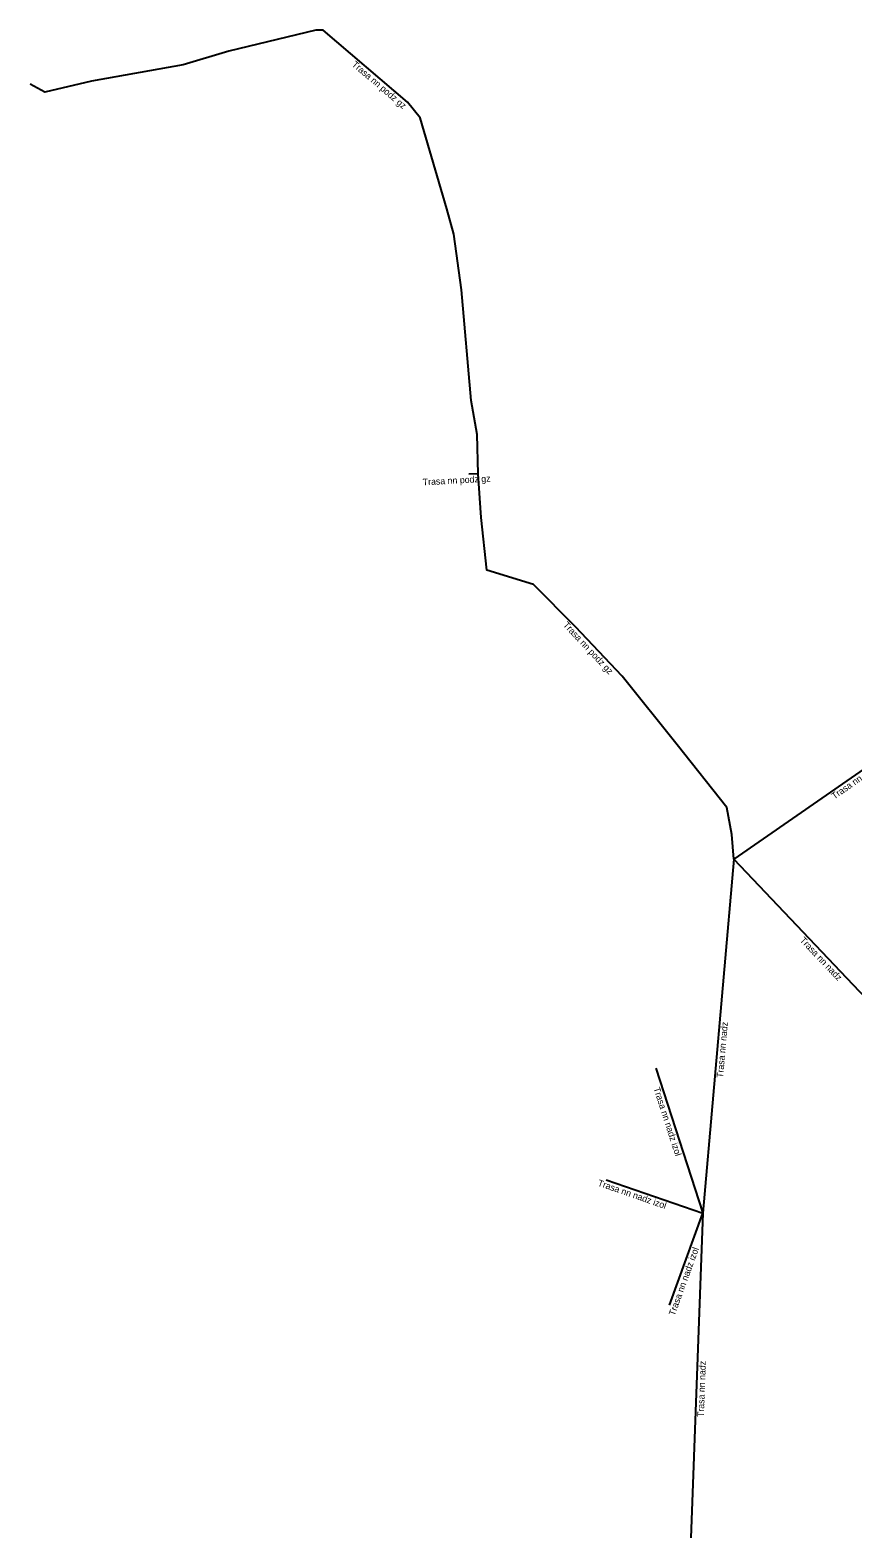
# Model space of a CAD drawing. Extents: x -772942 to -772530, y -1033745 to -1033298.
# Drawn here: x -772942.2 to -772879.6, y -1033618.3 to -1033503.6 of the extents above; entities that cross this region are included whole.
import ezdxf

# ---------------------------------------------------------------- set-up
doc = ezdxf.new("R2010")
doc.units = 0
doc.layers.add('Popiskový text - Ostatní atributy Trasy', color=7, linetype='Continuous')
doc.layers.add('Spojnice NN', color=7, linetype='Continuous')

msp = doc.modelspace()

# ---------------------------------------------------------------- linework, layer by layer
at = {"layer": 'Spojnice NN'}
for points in [[(-772908.07, -1033537.38), (-772908.15, -1033534.39), (-772908.62, -1033531.8), (-772909.34, -1033523.4), (-772909.93, -1033519.17), (-772910.45, -1033517.24), (-772912.49, -1033510.3), (-772913.45, -1033509.11), (-772919.87, -1033503.64), (-772920.43, -1033503.64), (-772927.05, -1033505.25), (-772930.52, -1033506.28), (-772937.51, -1033507.51), (-772941.05, -1033508.35), (-772942.17, -1033507.74)], [(-772908.07, -1033537.38), (-772908.78, -1033537.42)], [(-772888.63, -1033566.69), (-772888.76, -1033564.83), (-772889.14, -1033562.78), (-772892.94, -1033558.01), (-772897.13, -1033552.79), (-772900.67, -1033549.02), (-772903.87, -1033545.8), (-772907.42, -1033544.71), (-772907.85, -1033540.72), (-772908.07, -1033537.38)], [(-772868.87, -1033553.01), (-772888.63, -1033566.69)], [(-772888.63, -1033566.69), (-772890.99, -1033593.62)], [(-772888.63, -1033566.69), (-772873.36, -1033582.78)], [(-772894.55, -1033582.6), (-772890.99, -1033593.62)], [(-772898.33, -1033591.08), (-772890.99, -1033593.62)], [(-772893.51, -1033600.62), (-772890.99, -1033593.62)], [(-772890.99, -1033593.62), (-772891.89, -1033618.32)]]:
    msp.add_lwpolyline(points, dxfattribs=at)

# ---------------------------------------------------------------- texts
at = {"layer": 'Popiskový text - Ostatní atributy Trasy'}
for s, rotation, p in [('Trasa nn podz gz', 319.5682, (-772917.73, -1033506.32)), ('Trasa nn podz gz', 3.2245, (-772912.28, -1033538.27)), ('Trasa nn podz gz', 313.1979, (-772901.65, -1033548.92)), ('Trasa nn nadz', 34.7016, (-772880.97, -1033562.17)), ('Trasa nn nadz', 313.5022, (-772883.63, -1033572.9)), ('Trasa nn nadz', 84.9871, (-772889.44, -1033583.35)), ('Trasa nn nadz izol', 287.89, (-772894.74, -1033584.13)), ('Trasa nn nadz izol', 340.9131, (-772899.02, -1033591.53)), ('Trasa nn nadz izol', 70.2283, (-772893.12, -1033601.47)), ('Trasa nn nadz', 87.9275, (-772890.9, -1033609.14))]:
    msp.add_text(s, height=0.5, rotation=rotation, dxfattribs=at).set_placement(p)

doc.saveas('drawing.dxf')
